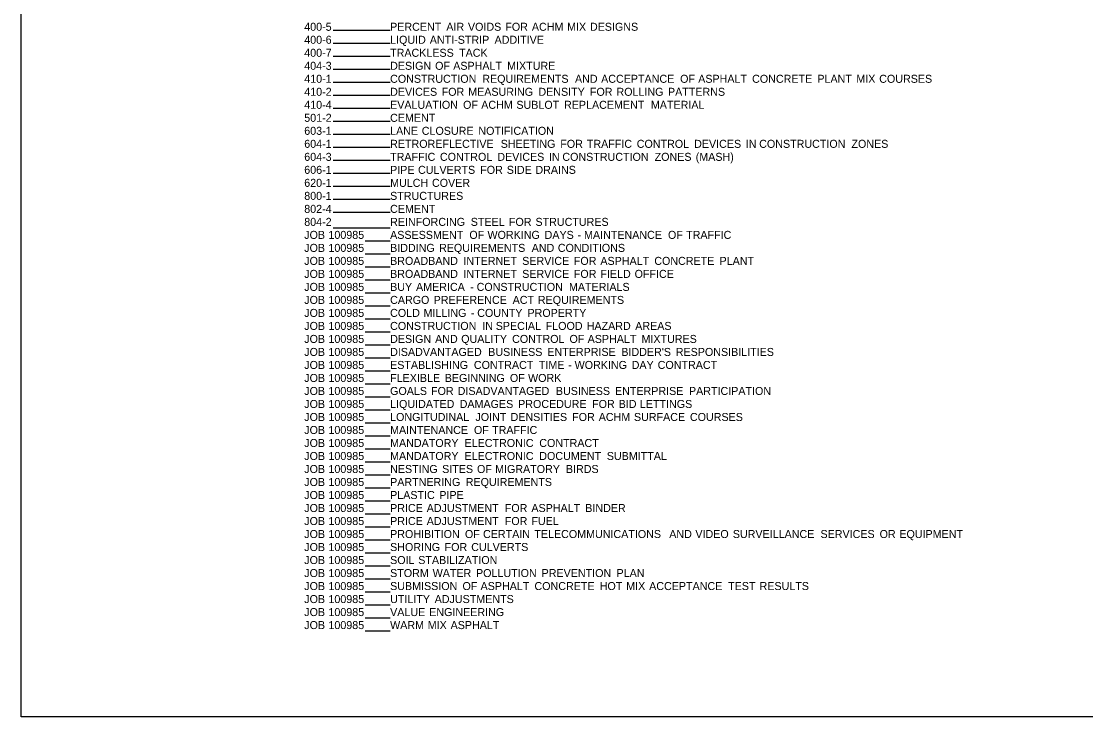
# Model space of a CAD drawing. Extents: x 1955683 to 1956002, y 566394 to 566602.
# Drawn here: x 1955683.4 to 1955842.9, y 566393.5 to 566497.8 of the extents above; entities that cross this region are included whole.
import ezdxf

# ---------------------------------------------------------------- set-up
doc = ezdxf.new("R2010")
doc.units = 0
for name, color, linetype in [('Default', 7, 'Continuous'), ('R_Border', 7, 'Continuous'), ('R_Border Prem', 7, 'Continuous')]:
    doc.layers.add(name, color=color, linetype=linetype)

msp = doc.modelspace()

# ---------------------------------------------------------------- linework, layer by layer
at = {"layer": 'R_Border'}
for p, q in [((1955730.1, 566496.44), (1955738.66, 566496.44)), ((1955730.1, 566494.49), (1955738.66, 566494.49)), ((1955730.1, 566492.54), (1955738.66, 566492.54)), ((1955730.1, 566490.59), (1955738.66, 566490.59)), ((1955730.1, 566488.64), (1955738.66, 566488.64)), ((1955730.1, 566486.69), (1955738.66, 566486.69)), ((1955730.1, 566484.74), (1955738.66, 566484.74)), ((1955730.1, 566482.79), (1955738.66, 566482.79)), ((1955730.1, 566480.84), (1955738.66, 566480.84)), ((1955730.1, 566478.89), (1955738.66, 566478.89)), ((1955730.1, 566476.94), (1955738.66, 566476.94)), ((1955730.1, 566474.99), (1955738.66, 566474.99)), ((1955730.1, 566473.04), (1955738.66, 566473.04)), ((1955730.1, 566471.09), (1955738.66, 566471.09)), ((1955730.1, 566469.14), (1955738.66, 566469.14)), ((1955730.1, 566466.82), (1955738.66, 566466.82)), ((1955734.91, 566464.87), (1955738.66, 566464.87)), ((1955734.91, 566462.92), (1955738.66, 566462.92)), ((1955734.91, 566460.97), (1955738.66, 566460.97)), ((1955734.91, 566459.02), (1955738.66, 566459.02)), ((1955734.91, 566457.07), (1955738.66, 566457.07)), ((1955734.91, 566455.12), (1955738.66, 566455.12)), ((1955734.91, 566453.17), (1955738.66, 566453.17)), ((1955734.91, 566451.22), (1955738.66, 566451.22)), ((1955734.91, 566449.28), (1955738.66, 566449.28)), ((1955734.91, 566447.32), (1955738.66, 566447.32)), ((1955734.91, 566445.37), (1955738.66, 566445.37)), ((1955734.91, 566443.42), (1955738.66, 566443.42)), ((1955734.91, 566441.47), (1955738.66, 566441.47)), ((1955734.91, 566439.52), (1955738.66, 566439.52)), ((1955734.91, 566437.57), (1955738.66, 566437.57)), ((1955734.91, 566435.62), (1955738.66, 566435.62)), ((1955734.91, 566433.67), (1955738.66, 566433.67)), ((1955734.91, 566431.72), (1955738.66, 566431.72)), ((1955734.91, 566429.77), (1955738.66, 566429.77)), ((1955734.91, 566427.82), (1955738.66, 566427.82)), ((1955734.91, 566425.87), (1955738.66, 566425.87)), ((1955734.91, 566423.92), (1955738.66, 566423.92)), ((1955734.91, 566421.97), (1955738.66, 566421.97)), ((1955734.91, 566420.02), (1955738.66, 566420.02)), ((1955734.91, 566418.07), (1955738.66, 566418.07)), ((1955734.91, 566416.13), (1955738.66, 566416.13)), ((1955734.91, 566414.17), (1955738.66, 566414.17)), ((1955734.91, 566412.22), (1955738.66, 566412.22)), ((1955734.91, 566410.27), (1955738.66, 566410.27)), ((1955734.91, 566408.32), (1955738.66, 566408.32)), ((1955734.91, 566406.37), (1955738.66, 566406.37))]:
    msp.add_line(p, q, dxfattribs=at)
at = {"layer": 'R_Border Prem'}
msp.add_lwpolyline([(1956002.45, 566561.79), (1956002.45, 566393.51), (1955683.38, 566393.51), (1955683.38, 566601.97), (1955920.19, 566601.97), (1955920.19, 566592.09), (1955955.71, 566592.09), (1955955.71, 566588.52), (1955959.35, 566588.52), (1955959.35, 566589.17), (1955974.89, 566589.17)], dxfattribs=at)

# ---------------------------------------------------------------- texts
at = {"layer": 'Default'}
for s, p in [('400-5', (1955725.79, 566496.35)), ('PERCENT', (1955738.66, 566496.35)), (' AIR', (1955746.64, 566496.35)), (' VOIDS', (1955749.88, 566496.35)), (' FOR', (1955755.48, 566496.35)), (' ACHM', (1955759.46, 566496.35)), (' MIX', (1955764.74, 566496.35)), (' DESIGNS', (1955768.17, 566496.35)), ('400-6', (1955725.79, 566494.4)), ('LIQUID', (1955738.66, 566494.4)), (' ANTI-STRIP', (1955744.16, 566494.4)), (' ADDITIVE', (1955753.87, 566494.4)), ('400-7', (1955725.79, 566492.45)), ('TRACKLESS', (1955738.66, 566492.45)), (' TACK', (1955748.55, 566492.45)), ('404-3', (1955725.79, 566490.5)), ('DESIGN', (1955738.66, 566490.5)), (' OF', (1955744.96, 566490.5)), (' ASPHALT', (1955747.67, 566490.5)), (' MIXTURE', (1955755.75, 566490.5)), ('410-1', (1955725.79, 566488.55)), ('CONSTRUCTION', (1955738.66, 566488.55)), (' REQUIREMENTS', (1955752.03, 566488.55)), (' AND', (1955765.92, 566488.55)), (' ACCEPTANCE', (1955769.84, 566488.55)), (' OF', (1955781.68, 566488.55)), (' ASPHALT', (1955784.39, 566488.55)), (' CONCRETE', (1955792.47, 566488.55)), (' PLANT', (1955802.25, 566488.55)), (' MIX', (1955808.09, 566488.55)), (' COURSES', (1955811.52, 566488.55)), ('410-2', (1955725.79, 566486.6)), ('DEVICES', (1955738.66, 566486.6)), (' FOR', (1955745.94, 566486.6)), (' MEASURING', (1955749.92, 566486.6)), (' DENSITY', (1955760.44, 566486.6)), (' FOR', (1955768.16, 566486.6)), (' ROLLING', (1955772.14, 566486.6)), (' PATTERNS', (1955779.86, 566486.6)), ('410-4', (1955725.79, 566484.65)), ('EVALUATION', (1955738.66, 566484.65)), (' OF', (1955749.15, 566484.65)), (' ACHM', (1955751.87, 566484.65)), (' SUBLOT', (1955757.14, 566484.65)), (' REPLACEMENT', (1955764.28, 566484.65)), (' MATERIAL', (1955777.3, 566484.65)), ('501-2', (1955725.79, 566482.7)), ('CEMENT', (1955738.66, 566482.7)), ('603-1', (1955725.79, 566480.75)), ('LANE', (1955738.66, 566480.75)), (' CLOSURE', (1955742.96, 566480.75)), (' NOTIFICATION', (1955751.44, 566480.75)), ('604-1', (1955725.79, 566478.8)), ('RETROREFLECTIVE', (1955738.66, 566478.8)), (' SHEETING', (1955754.79, 566478.8)), (' FOR', (1955763.72, 566478.8)), (' TRAFFIC', (1955767.7, 566478.8)), (' CONTROL', (1955775.18, 566478.8)), (' DEVICES', (1955783.78, 566478.8)), (' IN', (1955791.52, 566478.8)), (' CONSTRUCTION', (1955793.53, 566478.8)), (' ZONES', (1955807.36, 566478.8)), ('604-3', (1955725.79, 566476.85)), ('TRAFFIC', (1955738.66, 566476.85)), (' CONTROL', (1955745.68, 566476.85)), (' DEVICES', (1955754.28, 566476.85)), (' IN', (1955762.02, 566476.85)), (' CONSTRUCTION', (1955764.03, 566476.85)), (' ZONES', (1955777.86, 566476.85)), (' (MASH)', (1955784.02, 566476.85)), ('606-1', (1955725.79, 566474.9)), (' CULVERTS', (1955742.4, 566474.9)), (' FOR', (1955751.72, 566474.9)), (' SIDE', (1955755.7, 566474.9)), (' DRAINS', (1955759.99, 566474.9)), ('PIPE', (1955738.66, 566474.9)), ('620-1', (1955725.79, 566472.95)), ('MULCH', (1955738.66, 566472.95)), (' COVER', (1955744.49, 566472.95)), ('800-1', (1955725.79, 566471)), ('STRUCTURES', (1955738.66, 566471)), ('802-4', (1955725.79, 566469.05)), ('CEMENT', (1955738.66, 566469.05)), ('804-2', (1955725.79, 566467.1)), ('REINFORCING', (1955738.66, 566467.1)), (' STEEL', (1955750.3, 566467.1)), (' FOR', (1955756.02, 566467.1)), (' STRUCTURES', (1955760, 566467.1)), ('JOB', (1955725.79, 566465.15)), (' 100985', (1955728.97, 566465.15)), ('ASSESSMENT', (1955738.66, 566465.15)), (' OF', (1955750.09, 566465.15)), (' WORKING', (1955752.81, 566465.15)), (' DAYS', (1955761.37, 566465.15)), (' -', (1955766.31, 566465.15)), (' MAINTENANCE', (1955767.28, 566465.15)), (' OF', (1955779.86, 566465.15)), (' TRAFFIC', (1955782.58, 566465.15)), ('JOB', (1955725.79, 566463.2)), (' 100985', (1955728.97, 566463.2)), ('BIDDING', (1955738.66, 566463.2)), (' REQUIREMENTS', (1955745.55, 566463.2)), (' AND', (1955759.43, 566463.2)), (' CONDITIONS', (1955763.35, 566463.2)), ('JOB', (1955725.79, 566461.25)), (' 100985', (1955728.97, 566461.25)), ('BROADBAND', (1955738.66, 566461.25)), (' INTERNET', (1955749.2, 566461.25)), (' SERVICE', (1955758.01, 566461.25)), (' FOR', (1955765.75, 566461.25)), (' ASPHALT', (1955769.73, 566461.25)), (' CONCRETE', (1955777.81, 566461.25)), (' PLANT', (1955787.59, 566461.25)), ('JOB', (1955725.79, 566459.3)), (' 100985', (1955728.97, 566459.3)), ('BROADBAND', (1955738.66, 566459.3)), (' INTERNET', (1955749.2, 566459.3)), (' SERVICE', (1955758.01, 566459.3)), (' FOR', (1955765.75, 566459.3)), (' FIELD', (1955769.73, 566459.3)), (' OFFICE', (1955774.86, 566459.3)), ('JOB', (1955725.79, 566457.35)), (' 100985', (1955728.97, 566457.35)), (' AMERICA', (1955742.1, 566457.35)), (' CONSTRUCTION', (1955751.18, 566457.35)), (' MATERIALS', (1955765.02, 566457.35)), ('BUY', (1955738.66, 566457.35)), (' -', (1955750.21, 566457.35)), ('JOB', (1955725.79, 566455.4)), (' 100985', (1955728.97, 566455.4)), ('CARGO', (1955738.66, 566455.4)), (' PREFERENCE', (1955744.74, 566455.4)), (' ACT', (1955756.58, 566455.4)), (' REQUIREMENTS', (1955760.36, 566455.4)), ('JOB', (1955725.79, 566453.45)), (' 100985', (1955728.97, 566453.45)), ('COLD', (1955738.66, 566453.45)), (' MILLING', (1955743.23, 566453.45)), (' -', (1955750.3, 566453.45)), (' COUNTY', (1955751.27, 566453.45)), (' PROPERTY', (1955758.8, 566453.45)), ('JOB', (1955725.79, 566451.5)), (' 100985', (1955728.97, 566451.5)), ('CONSTRUCTION', (1955738.66, 566451.5)), (' IN', (1955752.03, 566451.5)), (' SPECIAL', (1955754.04, 566451.5)), (' FLOOD', (1955761.53, 566451.5)), (' HAZARD', (1955767.68, 566451.5)), (' AREAS', (1955774.95, 566451.5)), ('JOB', (1955725.79, 566449.55)), (' 100985', (1955728.97, 566449.55)), ('DESIGN', (1955738.66, 566449.55)), (' AND', (1955744.96, 566449.55)), (' QUALITY', (1955748.87, 566449.55)), (' CONTROL', (1955756.5, 566449.55)), (' OF', (1955765.1, 566449.55)), (' ASPHALT', (1955767.82, 566449.55)), (' MIXTURES', (1955775.89, 566449.55)), ('JOB', (1955725.79, 566447.6)), (' 100985', (1955728.97, 566447.6)), ('DISADVANTAGED', (1955738.66, 566447.6)), (' BUSINESS', (1955752.92, 566447.6)), (' ENTERPRISE', (1955761.78, 566447.6)), (" BIDDER'S", (1955772.87, 566447.6)), (' RESPONSIBILITIES', (1955781.03, 566447.6)), ('JOB', (1955725.79, 566445.65)), (' 100985', (1955728.97, 566445.65)), ('ESTABLISHING', (1955738.66, 566445.65)), (' CONTRACT', (1955750.77, 566445.65)), (' TIME', (1955760.51, 566445.65)), (' -', (1955764.89, 566445.65)), (' WORKING', (1955765.87, 566445.65)), (' DAY', (1955774.42, 566445.65)), (' CONTRACT', (1955778.32, 566445.65)), ('JOB', (1955725.79, 566443.7)), (' 100985', (1955728.97, 566443.7)), ('FLEXIBLE', (1955738.66, 566443.7)), (' BEGINNING', (1955746.4, 566443.7)), (' OF', (1955756.17, 566443.7)), (' WORK', (1955758.89, 566443.7)), ('JOB', (1955725.79, 566441.75)), (' 100985', (1955728.97, 566441.75)), ('GOALS', (1955738.66, 566441.75)), (' FOR', (1955744.35, 566441.75)), (' DISADVANTAGED', (1955748.34, 566441.75)), (' BUSINESS', (1955763.06, 566441.75)), (' ENTERPRISE', (1955771.92, 566441.75)), (' PARTICIPATION', (1955783.01, 566441.75)), ('JOB', (1955725.79, 566439.8)), (' 100985', (1955728.97, 566439.8)), ('LIQUIDATED', (1955738.66, 566439.8)), (' DAMAGES', (1955748.64, 566439.8)), (' PROCEDURE', (1955757.4, 566439.8)), (' FOR', (1955768.49, 566439.8)), (' LETTINGS', (1955775.65, 566439.8)), (' BID', (1955772.47, 566439.8)), ('JOB', (1955725.79, 566437.85)), (' 100985', (1955728.97, 566437.85)), ('LONGITUDINAL', (1955738.66, 566437.85)), (' JOINT', (1955751, 566437.85)), (' DENSITIES', (1955756.27, 566437.85)), (' FOR', (1955765.5, 566437.85)), (' ACHM', (1955769.48, 566437.85)), (' SURFACE', (1955774.76, 566437.85)), (' COURSES', (1955783.15, 566437.85)), ('JOB', (1955725.79, 566435.9)), (' 100985', (1955728.97, 566435.9)), ('MAINTENANCE', (1955738.66, 566435.9)), (' OF', (1955750.78, 566435.9)), (' TRAFFIC', (1955753.5, 566435.9)), ('JOB', (1955725.79, 566433.95)), (' 100985', (1955728.97, 566433.95)), ('MANDATORY', (1955738.66, 566433.95)), (' ELECTRONIC', (1955749.37, 566433.95)), (' CONTRACT', (1955760.57, 566433.95)), ('JOB', (1955725.79, 566432)), (' 100985', (1955728.97, 566432)), ('MANDATORY', (1955738.66, 566432)), (' ELECTRONIC', (1955749.37, 566432)), (' DOCUMENT', (1955760.57, 566432)), (' SUBMITTAL', (1955770.69, 566432)), ('JOB', (1955725.79, 566430.05)), (' 100985', (1955728.97, 566430.05)), ('NESTING', (1955738.66, 566430.05)), (' SITES', (1955746.01, 566430.05)), (' OF', (1955751.24, 566430.05)), (' MIGRATORY', (1955753.95, 566430.05)), (' BIRDS', (1955764.56, 566430.05)), ('JOB', (1955725.79, 566428.1)), (' 100985', (1955728.97, 566428.1)), ('PARTNERING', (1955738.66, 566428.1)), (' REQUIREMENTS', (1955749.55, 566428.1)), ('JOB', (1955725.79, 566426.15)), (' 100985', (1955728.97, 566426.15)), ('PLASTIC', (1955738.66, 566426.15)), (' PIPE', (1955745.59, 566426.15)), ('JOB', (1955725.79, 566424.2)), (' 100985', (1955728.97, 566424.2)), ('PRICE', (1955738.66, 566424.2)), (' ADJUSTMENT', (1955743.7, 566424.2)), (' FOR', (1955755.4, 566424.2)), (' ASPHALT', (1955759.39, 566424.2)), (' BINDER', (1955767.46, 566424.2)), ('JOB', (1955725.79, 566422.25)), (' 100985', (1955728.97, 566422.25)), ('PRICE', (1955738.66, 566422.25)), (' ADJUSTMENT', (1955743.7, 566422.25)), (' FOR', (1955755.4, 566422.25)), (' FUEL', (1955759.39, 566422.25)), ('JOB', (1955725.79, 566420.3)), (' 100985', (1955728.97, 566420.3)), ('PROHIBITION', (1955738.66, 566420.3)), (' OF', (1955749.43, 566420.3)), (' CERTAIN', (1955752.14, 566420.3)), (' TELECOMMUNICATIONS', (1955759.83, 566420.3)), (' AND', (1955780.05, 566420.3)), (' VIDEO', (1955783.97, 566420.3)), (' SURVEILLANCE', (1955789.58, 566420.3)), (' SERVICES', (1955802.72, 566420.3)), (' OR', (1955811.58, 566420.3)), (' EQUIPMENT', (1955814.54, 566420.3)), ('JOB', (1955725.79, 566418.35)), (' 100985', (1955728.97, 566418.35)), ('SHORING', (1955738.66, 566418.35)), (' FOR', (1955746.38, 566418.35)), (' CULVERTS', (1955750.37, 566418.35)), ('JOB', (1955725.79, 566416.4)), (' 100985', (1955728.97, 566416.4)), ('SOIL', (1955738.66, 566416.4)), (' STABILIZATION', (1955742.43, 566416.4)), ('JOB', (1955725.79, 566414.45)), (' 100985', (1955728.97, 566414.45)), ('STORM', (1955738.66, 566414.45)), (' WATER', (1955744.59, 566414.45)), (' POLLUTION', (1955751.09, 566414.45)), (' PREVENTION', (1955760.92, 566414.45)), (' PLAN', (1955772.15, 566414.45)), ('JOB', (1955725.79, 566412.5)), (' 100985', (1955728.97, 566412.5)), ('SUBMISSION', (1955738.66, 566412.5)), (' OF', (1955749.06, 566412.5)), (' ASPHALT', (1955751.77, 566412.5)), (' CONCRETE', (1955759.85, 566412.5)), (' HOT', (1955769.63, 566412.5)), (' MIX', (1955773.6, 566412.5)), (' ACCEPTANCE', (1955777.04, 566412.5)), (' TEST', (1955788.88, 566412.5)), (' RESULTS', (1955793.59, 566412.5)), ('JOB', (1955725.79, 566410.55)), (' 100985', (1955728.97, 566410.55)), ('UTILITY', (1955738.66, 566410.55)), (' ADJUSTMENTS', (1955744.89, 566410.55)), ('JOB', (1955725.79, 566408.6)), (' 100985', (1955728.97, 566408.6)), ('VALUE', (1955738.66, 566408.6)), (' ENGINEERING', (1955744.07, 566408.6)), ('JOB', (1955725.79, 566406.65)), (' 100985', (1955728.97, 566406.65)), ('WARM', (1955738.66, 566406.65)), (' MIX', (1955743.85, 566406.65)), (' ASPHALT', (1955747.28, 566406.65))]:
    msp.add_text(s, height=1.2, dxfattribs=at).set_placement(p)

doc.saveas('drawing.dxf')
